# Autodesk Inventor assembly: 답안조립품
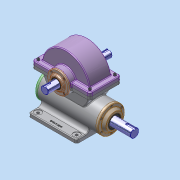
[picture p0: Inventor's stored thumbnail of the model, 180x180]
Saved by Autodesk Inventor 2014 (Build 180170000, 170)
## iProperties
Created: 2023-12
Part Number: 답안조립품
Document SubType Name: Assembly
Designer: dg
Author: dg
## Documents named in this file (14)
- C:\Users\dg\Desktop\631208V1011\답안조립품.iam
- C:\Users\dg\Desktop\631208V1011\본체.ipt
- C:\Users\dg\Desktop\631208V1011\깊은 홈 볼 베어링 6209.ipt
- C:\Users\dg\Desktop\631208V1011\웜 샤프트.ipt
- C:\Users\dg\Desktop\631208V1011\뒤커버.ipt
- C:\Users\dg\Desktop\631208V1011\앞커버.ipt
- C:\Users\dg\Desktop\631208V1011\육각 소켓 머리 볼트 M5 x 12.ipt
- C:\Users\dg\Desktop\631208V1011\오일 실 35 55 11.ipt
- C:\Users\dg\Desktop\631208V1011\깊은 홈 볼 베어링 6206.ipt
- C:\Users\dg\Desktop\631208V1011\웜 휠.ipt
- C:\Users\dg\Desktop\631208V1011\본체 커버.ipt
- C:\Users\dg\Desktop\631208V1011\육각 소켓 머리 볼트 M6 x 20.ipt
- C:\Users\dg\Desktop\631208V1011\서브커버.ipt
- C:\Users\dg\Desktop\631208V1011\오일 실 30 42 7.ipt
